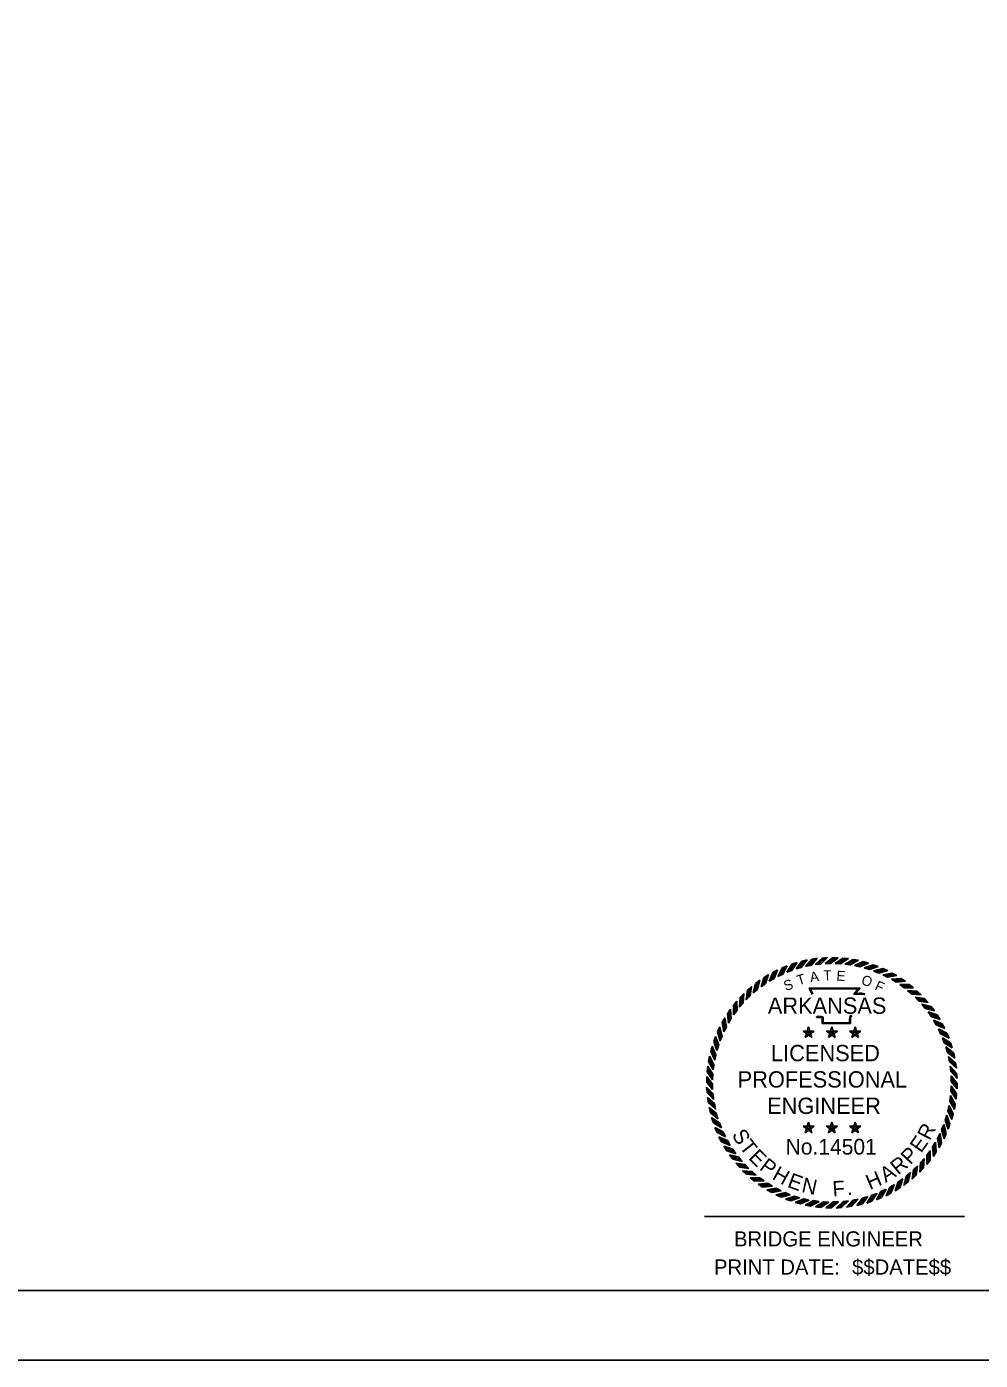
# Model space of a CAD drawing. Extents: x 188 to 14744886, y 129 to 1829278.
# Drawn here: x 206.58 to 214.44, y 128.51 to 139.51 of the extents above; entities that cross this region are included whole.
import ezdxf

# ---------------------------------------------------------------- set-up
doc = ezdxf.new("R2010")
doc.units = 0
for name, color, linetype in [('B_border', 7, 'Continuous'), ('B_Print_Date_Text', 7, 'Continuous'), ('B_Text', 7, 'Continuous'), ('R_Border', 7, 'Continuous'), ('STAMP', 7, 'Continuous')]:
    doc.layers.add(name, color=color, linetype=linetype)

msp = doc.modelspace()

# ---------------------------------------------------------------- linework, layer by layer
at = {"layer": 'B_border'}
msp.add_line((212.167, 129.699), (214.309, 129.699), dxfattribs=at)
msp.add_line((212.167, 129.699), (214.309, 129.699), dxfattribs=at)
at = {"layer": 'R_Border'}
msp.add_line((221.306, 129.091), (189.399, 129.091), dxfattribs=at)
msp.add_lwpolyline([(187.883, 150.514), (221.883, 150.514), (221.883, 128.514), (187.883, 128.514)], close=True, dxfattribs=at)
at = {"layer": 'STAMP'}
for p, q in [((212.886, 131.781), (212.929, 131.796)), ((212.968, 131.805), (213.012, 131.816)), ((213.052, 131.822), (213.096, 131.83)), ((213.079, 131.778), (213.124, 131.782)), ((213.136, 131.832), (213.181, 131.836)), ((213.16, 131.786), (213.206, 131.786)), ((213.222, 131.834), (213.267, 131.834)), ((213.242, 131.787), (213.287, 131.784)), ((213.307, 131.831), (213.352, 131.828)), ((213.323, 131.782), (213.368, 131.775)), ((213.391, 131.82), (213.436, 131.813)), ((213.475, 131.802), (213.519, 131.791)), ((212.656, 131.67), (212.694, 131.695)), ((212.73, 131.713), (212.769, 131.735)), ((212.77, 131.681), (212.811, 131.699)), ((212.807, 131.75), (212.848, 131.769)), ((212.844, 131.715), (212.887, 131.73)), ((212.921, 131.742), (212.964, 131.754)), ((212.999, 131.764), (213.044, 131.771)), ((213.403, 131.77), (213.447, 131.759)), ((213.482, 131.751), (213.526, 131.737)), ((213.556, 131.777), (213.599, 131.763)), ((213.56, 131.726), (213.602, 131.708)), ((213.635, 131.694), (213.675, 131.673)), ((213.636, 131.746), (213.677, 131.728)), ((213.712, 131.708), (213.752, 131.687)), ((212.521, 131.566), (212.554, 131.597)), ((212.568, 131.544), (212.604, 131.573)), ((212.587, 131.621), (212.622, 131.649)), ((212.632, 131.595), (212.669, 131.621)), ((212.699, 131.641), (212.739, 131.663)), ((213.707, 131.657), (213.745, 131.632)), ((213.776, 131.613), (213.812, 131.586)), ((213.785, 131.664), (213.823, 131.64)), ((213.841, 131.564), (213.875, 131.534)), ((213.854, 131.614), (213.89, 131.587)), ((212.405, 131.441), (212.433, 131.477)), ((212.455, 131.428), (212.485, 131.461)), ((212.461, 131.506), (212.491, 131.539)), ((212.509, 131.488), (212.542, 131.519)), ((213.902, 131.51), (213.933, 131.477)), ((213.919, 131.559), (213.953, 131.528)), ((213.958, 131.451), (213.986, 131.416)), ((213.979, 131.498), (214.01, 131.465)), ((212.355, 131.372), (212.38, 131.41)), ((212.406, 131.363), (212.434, 131.399)), ((214.009, 131.388), (214.034, 131.35)), ((214.034, 131.433), (214.062, 131.397)), ((214.083, 131.363), (214.108, 131.325)), ((212.274, 131.222), (212.291, 131.264)), ((212.311, 131.299), (212.333, 131.339)), ((212.325, 131.222), (212.346, 131.262)), ((212.363, 131.294), (212.387, 131.332)), ((213.07, 131.23), (212.979, 131.23)), ((212.979, 131.23), (213.053, 131.177)), ((213.024, 131.264), (212.996, 131.177)), ((212.996, 131.177), (213.07, 131.23)), ((213.052, 131.177), (213.024, 131.264)), ((213.262, 131.23), (213.17, 131.23)), ((213.171, 131.23), (213.244, 131.177)), ((213.216, 131.264), (213.188, 131.177)), ((213.188, 131.177), (213.262, 131.23)), ((213.244, 131.177), (213.216, 131.264)), ((213.454, 131.23), (213.362, 131.23)), ((213.362, 131.23), (213.436, 131.177)), ((213.408, 131.264), (213.38, 131.177)), ((213.38, 131.177), (213.454, 131.23)), ((213.436, 131.177), (213.408, 131.264)), ((214.054, 131.32), (214.076, 131.281)), ((214.094, 131.249), (214.113, 131.208)), ((214.126, 131.29), (214.148, 131.25)), ((212.242, 131.143), (212.256, 131.186)), ((212.293, 131.147), (212.311, 131.188)), ((213.018, 131.216), (213.031, 131.216)), ((213.024, 131.221), (213.024, 131.209)), ((213.21, 131.216), (213.223, 131.216)), ((213.216, 131.221), (213.216, 131.209)), ((213.402, 131.216), (213.415, 131.216)), ((213.408, 131.221), (213.408, 131.209)), ((214.128, 131.175), (214.143, 131.133)), ((214.163, 131.213), (214.182, 131.171)), ((214.194, 131.133), (214.209, 131.09)), ((212.199, 130.978), (212.206, 131.023)), ((212.217, 131.061), (212.228, 131.105)), ((212.25, 130.99), (212.26, 131.034)), ((212.268, 131.069), (212.283, 131.112)), ((214.156, 131.099), (214.167, 131.055)), ((214.177, 131.02), (214.185, 130.976)), ((214.218, 131.051), (214.229, 131.008)), ((212.188, 130.894), (212.192, 130.939)), ((212.237, 130.91), (212.244, 130.954)), ((214.191, 130.94), (214.196, 130.895)), ((214.235, 130.968), (214.243, 130.923)), ((212.184, 130.808), (212.184, 130.854)), ((212.232, 130.828), (212.235, 130.874)), ((212.233, 130.747), (212.233, 130.792)), ((214.199, 130.859), (214.2, 130.814)), ((214.245, 130.883), (214.249, 130.838)), ((214.248, 130.798), (214.248, 130.753)), ((212.188, 130.723), (212.183, 130.768)), ((212.198, 130.638), (212.19, 130.683)), ((212.241, 130.666), (212.237, 130.711)), ((214.195, 130.697), (214.188, 130.652)), ((214.201, 130.778), (214.197, 130.733)), ((214.244, 130.713), (214.241, 130.668)), ((212.215, 130.555), (212.203, 130.599)), ((212.256, 130.586), (212.248, 130.631)), ((214.183, 130.616), (214.172, 130.572)), ((214.233, 130.628), (214.226, 130.583)), ((212.239, 130.473), (212.224, 130.516)), ((212.277, 130.507), (212.265, 130.551)), ((212.305, 130.431), (212.29, 130.474)), ((213.024, 130.477), (212.996, 130.39)), ((213.052, 130.39), (213.024, 130.477)), ((213.216, 130.477), (213.188, 130.39)), ((213.244, 130.39), (213.216, 130.477)), ((213.408, 130.477), (213.38, 130.39)), ((213.436, 130.39), (213.408, 130.477)), ((214.164, 130.537), (214.15, 130.494)), ((214.19, 130.463), (214.176, 130.42)), ((214.215, 130.545), (214.204, 130.501)), ((212.269, 130.393), (212.251, 130.435)), ((212.306, 130.317), (212.284, 130.356)), ((212.339, 130.357), (212.32, 130.398)), ((213.07, 130.444), (212.979, 130.444)), ((212.979, 130.444), (213.053, 130.39)), ((212.996, 130.39), (213.07, 130.444)), ((213.018, 130.429), (213.031, 130.429)), ((213.024, 130.434), (213.024, 130.422)), ((213.262, 130.444), (213.17, 130.444)), ((213.171, 130.444), (213.244, 130.39)), ((213.188, 130.39), (213.262, 130.444)), ((213.21, 130.429), (213.223, 130.429)), ((213.216, 130.434), (213.216, 130.422)), ((213.454, 130.444), (213.362, 130.444)), ((213.362, 130.444), (213.436, 130.39)), ((213.38, 130.39), (213.454, 130.444)), ((213.402, 130.429), (213.415, 130.429)), ((213.408, 130.434), (213.408, 130.422)), ((214.108, 130.384), (214.086, 130.344)), ((214.139, 130.46), (214.121, 130.418)), ((214.159, 130.384), (214.141, 130.342)), ((212.35, 130.243), (212.325, 130.281)), ((212.378, 130.286), (212.356, 130.326)), ((212.424, 130.218), (212.399, 130.256)), ((214.026, 130.243), (213.999, 130.207)), ((214.07, 130.312), (214.045, 130.274)), ((214.121, 130.307), (214.1, 130.267)), ((212.399, 130.174), (212.371, 130.209)), ((212.454, 130.108), (212.423, 130.141)), ((212.475, 130.155), (212.447, 130.191)), ((213.977, 130.178), (213.947, 130.145)), ((214.027, 130.165), (214, 130.129)), ((214.077, 130.234), (214.053, 130.196)), ((212.514, 130.048), (212.48, 130.078)), ((212.531, 130.096), (212.5, 130.129)), ((212.592, 130.042), (212.558, 130.072)), ((212.657, 129.993), (212.621, 130.02)), ((213.864, 130.062), (213.829, 130.034)), ((213.911, 130.04), (213.878, 130.009)), ((213.923, 130.118), (213.89, 130.087)), ((213.972, 130.1), (213.941, 130.067)), ((212.578, 129.992), (212.542, 130.02)), ((212.648, 129.942), (212.609, 129.967)), ((212.721, 129.898), (212.681, 129.919)), ((212.725, 129.949), (212.687, 129.974)), ((212.798, 129.912), (212.758, 129.933)), ((213.662, 129.925), (213.621, 129.907)), ((213.733, 129.965), (213.694, 129.943)), ((213.776, 129.936), (213.739, 129.911)), ((213.801, 130.011), (213.763, 129.986)), ((213.846, 129.986), (213.81, 129.958)), ((212.797, 129.86), (212.755, 129.878)), ((212.873, 129.88), (212.831, 129.898)), ((212.876, 129.829), (212.833, 129.843)), ((212.95, 129.855), (212.907, 129.869)), ((212.958, 129.804), (212.914, 129.815)), ((213.029, 129.836), (212.985, 129.847)), ((213.11, 129.824), (213.065, 129.831)), ((213.191, 129.819), (213.146, 129.822)), ((213.272, 129.82), (213.227, 129.82)), ((213.353, 129.828), (213.308, 129.824)), ((213.433, 129.843), (213.389, 129.835)), ((213.464, 129.802), (213.421, 129.79)), ((213.512, 129.864), (213.468, 129.852)), ((213.546, 129.826), (213.504, 129.81)), ((213.588, 129.891), (213.546, 129.876)), ((213.626, 129.856), (213.585, 129.838)), ((213.703, 129.893), (213.663, 129.871)), ((213.041, 129.786), (212.997, 129.793)), ((213.126, 129.775), (213.081, 129.779)), ((213.211, 129.771), (213.166, 129.771)), ((213.296, 129.774), (213.251, 129.77)), ((213.381, 129.785), (213.336, 129.777))]:
    msp.add_line(p, q, dxfattribs=at)
for points in [[(212.844, 131.715), (212.886, 131.781)], [(212.858, 131.719), (212.9, 131.785)], [(212.873, 131.725), (212.915, 131.791)], [(212.887, 131.73), (212.929, 131.796)], [(212.921, 131.742), (212.968, 131.805)], [(212.935, 131.746), (212.982, 131.808)], [(212.95, 131.75), (212.997, 131.812)], [(212.964, 131.754), (213.012, 131.816)], [(212.999, 131.763), (213.052, 131.822)], [(213.014, 131.766), (213.066, 131.824)], [(213.029, 131.769), (213.081, 131.827)], [(213.044, 131.771), (213.096, 131.83)], [(213.079, 131.778), (213.136, 131.832)], [(213.094, 131.779), (213.151, 131.833)], [(213.109, 131.781), (213.166, 131.835)], [(213.124, 131.782), (213.181, 131.836)], [(213.16, 131.786), (213.222, 131.834)], [(213.175, 131.786), (213.236, 131.834)], [(213.19, 131.786), (213.252, 131.834)], [(213.206, 131.786), (213.267, 131.834)], [(213.242, 131.787), (213.307, 131.831)], [(213.256, 131.786), (213.321, 131.83)], [(213.272, 131.785), (213.337, 131.829)], [(213.287, 131.784), (213.352, 131.828)], [(213.323, 131.782), (213.391, 131.82)], [(213.337, 131.78), (213.406, 131.818)], [(213.353, 131.777), (213.421, 131.815)], [(213.368, 131.775), (213.436, 131.813)], [(213.403, 131.77), (213.475, 131.802)], [(213.417, 131.766), (213.489, 131.798)], [(213.433, 131.763), (213.504, 131.795)], [(213.447, 131.759), (213.519, 131.791)], [(212.644, 131.603), (212.669, 131.678)], [(212.657, 131.612), (212.681, 131.687)], [(212.669, 131.621), (212.694, 131.695)], [(212.699, 131.641), (212.73, 131.713)], [(212.712, 131.648), (212.743, 131.72)], [(212.725, 131.656), (212.756, 131.728)], [(212.739, 131.663), (212.769, 131.735)], [(212.77, 131.681), (212.807, 131.75)], [(212.783, 131.687), (212.82, 131.756)], [(212.798, 131.693), (212.834, 131.763)], [(212.811, 131.699), (212.848, 131.769)], [(213.482, 131.751), (213.556, 131.777)], [(213.496, 131.746), (213.57, 131.773)], [(213.511, 131.742), (213.585, 131.768)], [(213.525, 131.737), (213.599, 131.763)], [(213.56, 131.726), (213.635, 131.746)], [(213.573, 131.72), (213.649, 131.74)], [(213.588, 131.714), (213.663, 131.734)], [(213.602, 131.708), (213.677, 131.728)], [(213.635, 131.694), (213.712, 131.708)], [(213.648, 131.687), (213.725, 131.701)], [(213.662, 131.68), (213.739, 131.694)], [(213.675, 131.673), (213.752, 131.687)], [(212.509, 131.488), (212.521, 131.566)], [(212.52, 131.498), (212.532, 131.576)], [(212.531, 131.509), (212.543, 131.587)], [(212.542, 131.519), (212.554, 131.597)], [(212.568, 131.544), (212.587, 131.62)], [(212.58, 131.553), (212.598, 131.629)], [(212.592, 131.563), (212.61, 131.639)], [(212.604, 131.573), (212.622, 131.649)], [(212.632, 131.595), (212.656, 131.67)], [(213.053, 131.532), (213.029, 131.584), (213.447, 131.584), (213.412, 131.54), (213.44, 131.541), (213.464, 131.541), (213.487, 131.538)], [(213.059, 131.534), (213.04, 131.577), (213.433, 131.577), (213.398, 131.533), (213.44, 131.534), (213.463, 131.534), (213.487, 131.532)], [(213.707, 131.657), (213.785, 131.664)], [(213.719, 131.649), (213.797, 131.656)], [(213.733, 131.641), (213.811, 131.648)], [(213.745, 131.632), (213.823, 131.64)], [(213.776, 131.613), (213.854, 131.614)], [(213.787, 131.604), (213.866, 131.605)], [(213.8, 131.595), (213.878, 131.596)], [(213.812, 131.586), (213.89, 131.587)], [(213.841, 131.564), (213.919, 131.559)], [(212.415, 131.374), (212.414, 131.452)], [(212.424, 131.387), (212.423, 131.465)], [(212.434, 131.399), (212.433, 131.477)], [(212.455, 131.428), (212.461, 131.506)], [(212.465, 131.438), (212.471, 131.516)], [(212.475, 131.45), (212.481, 131.528)], [(212.485, 131.461), (212.491, 131.539)], [(213.852, 131.554), (213.93, 131.549)], [(213.863, 131.544), (213.941, 131.539)], [(213.875, 131.534), (213.953, 131.528)], [(213.902, 131.51), (213.979, 131.498)], [(213.911, 131.499), (213.989, 131.487)], [(213.922, 131.488), (214, 131.476)], [(213.933, 131.477), (214.01, 131.465)], [(213.958, 131.451), (214.034, 131.433)], [(212.363, 131.294), (212.355, 131.372)], [(212.371, 131.306), (212.363, 131.384)], [(212.379, 131.319), (212.372, 131.397)], [(212.387, 131.332), (212.38, 131.41)], [(212.406, 131.363), (212.405, 131.441)], [(213.381, 131.357), (213.374, 131.351), (213.371, 131.342), (213.369, 131.321), (213.369, 131.292), (213.136, 131.292), (213.136, 131.331), (213.136, 131.339), (213.127, 131.342), (213.093, 131.342), (213.088, 131.351)], [(213.377, 131.362), (213.368, 131.355), (213.365, 131.343), (213.362, 131.321), (213.362, 131.298), (213.143, 131.298), (213.143, 131.331), (213.143, 131.344), (213.128, 131.349), (213.097, 131.349), (213.093, 131.355)], [(213.967, 131.44), (214.043, 131.421)], [(213.977, 131.428), (214.053, 131.409)], [(213.986, 131.416), (214.062, 131.397)], [(214.009, 131.388), (214.083, 131.363)], [(214.017, 131.376), (214.091, 131.351)], [(214.026, 131.363), (214.1, 131.338)], [(214.034, 131.35), (214.108, 131.325)], [(212.299, 131.16), (212.279, 131.236)], [(212.305, 131.175), (212.285, 131.25)], [(212.311, 131.188), (212.291, 131.264)], [(212.325, 131.222), (212.311, 131.299)], [(212.332, 131.234), (212.318, 131.312)], [(212.339, 131.249), (212.325, 131.326)], [(212.346, 131.262), (212.333, 131.339)], [(214.054, 131.32), (214.126, 131.29)], [(214.061, 131.307), (214.133, 131.277)], [(214.069, 131.294), (214.141, 131.263)], [(214.076, 131.281), (214.148, 131.25)], [(214.094, 131.249), (214.163, 131.213)], [(214.1, 131.236), (214.169, 131.199)], [(212.268, 131.069), (212.242, 131.143)], [(212.273, 131.083), (212.247, 131.157)], [(212.278, 131.098), (212.251, 131.172)], [(212.283, 131.112), (212.256, 131.186)], [(212.294, 131.147), (212.274, 131.222)], [(214.107, 131.222), (214.176, 131.185)], [(214.113, 131.208), (214.182, 131.171)], [(214.128, 131.175), (214.194, 131.133)], [(214.133, 131.162), (214.199, 131.119)], [(214.138, 131.147), (214.204, 131.105)], [(214.143, 131.133), (214.209, 131.09)], [(212.244, 130.954), (212.206, 131.023)], [(212.25, 130.99), (212.217, 131.061)], [(212.253, 131.004), (212.221, 131.076)], [(212.257, 131.02), (212.224, 131.091)], [(212.26, 131.034), (212.228, 131.105)], [(214.155, 131.099), (214.218, 131.051)], [(214.159, 131.085), (214.221, 131.037)], [(214.163, 131.07), (214.226, 131.022)], [(214.167, 131.055), (214.229, 131.007)], [(214.177, 131.02), (214.235, 130.968)], [(212.234, 130.859), (212.19, 130.924)], [(212.233, 130.843), (212.19, 130.908)], [(212.235, 130.874), (212.192, 130.939)], [(212.237, 130.91), (212.199, 130.978)], [(212.24, 130.924), (212.202, 130.992)], [(212.242, 130.94), (212.204, 131.008)], [(214.179, 131.006), (214.237, 130.953)], [(214.182, 130.99), (214.24, 130.938)], [(214.185, 130.976), (214.243, 130.923)], [(214.191, 130.94), (214.245, 130.883)], [(214.193, 130.926), (214.246, 130.869)], [(214.194, 130.91), (214.248, 130.853)], [(212.233, 130.792), (212.184, 130.854)], [(212.233, 130.777), (212.184, 130.839)], [(212.233, 130.762), (212.185, 130.823)], [(212.233, 130.747), (212.185, 130.808)], [(212.232, 130.828), (212.188, 130.893)], [(214.196, 130.895), (214.249, 130.838)], [(214.199, 130.859), (214.248, 130.798)], [(214.199, 130.845), (214.248, 130.783)], [(214.2, 130.829), (214.249, 130.768)], [(214.2, 130.814), (214.249, 130.753)], [(212.237, 130.711), (212.183, 130.768)], [(212.238, 130.696), (212.185, 130.753)], [(212.24, 130.681), (212.186, 130.738)], [(212.241, 130.666), (212.188, 130.723)], [(212.248, 130.631), (212.19, 130.683)], [(214.193, 130.682), (214.231, 130.614)], [(214.195, 130.697), (214.233, 130.628)], [(214.197, 130.733), (214.241, 130.667)], [(214.199, 130.763), (214.243, 130.698)], [(214.199, 130.748), (214.242, 130.682)], [(214.201, 130.778), (214.244, 130.713)], [(212.25, 130.616), (212.192, 130.668)], [(212.253, 130.6), (212.195, 130.653)], [(212.256, 130.586), (212.198, 130.638)], [(212.265, 130.551), (212.203, 130.599)], [(212.269, 130.537), (212.207, 130.584)], [(214.172, 130.572), (214.205, 130.501)], [(214.176, 130.587), (214.208, 130.515)], [(214.179, 130.602), (214.212, 130.531)], [(214.183, 130.616), (214.215, 130.545)], [(214.188, 130.652), (214.226, 130.583)], [(214.191, 130.667), (214.229, 130.598)], [(212.274, 130.522), (212.211, 130.569)], [(212.277, 130.507), (212.215, 130.555)], [(212.29, 130.474), (212.224, 130.516)], [(212.294, 130.459), (212.228, 130.501)], [(212.3, 130.445), (212.234, 130.487)], [(212.305, 130.431), (212.239, 130.473)], [(214.15, 130.494), (214.176, 130.42)], [(214.155, 130.508), (214.181, 130.434)], [(214.16, 130.523), (214.186, 130.449)], [(214.164, 130.537), (214.19, 130.463)], [(212.32, 130.398), (212.251, 130.435)], [(212.326, 130.384), (212.257, 130.421)], [(212.333, 130.37), (212.263, 130.407)], [(212.339, 130.357), (212.269, 130.393)], [(212.356, 130.326), (212.284, 130.356)], [(214.094, 130.358), (214.107, 130.281)], [(214.101, 130.372), (214.114, 130.295)], [(214.108, 130.385), (214.121, 130.307)], [(214.121, 130.418), (214.141, 130.342)], [(214.127, 130.432), (214.147, 130.356)], [(214.133, 130.446), (214.153, 130.371)], [(214.139, 130.46), (214.159, 130.384)], [(212.364, 130.312), (212.292, 130.343)], [(212.371, 130.299), (212.299, 130.329)], [(212.378, 130.286), (212.306, 130.317)], [(212.399, 130.256), (212.324, 130.281)], [(212.407, 130.244), (212.333, 130.268)], [(212.416, 130.231), (212.342, 130.255)], [(212.424, 130.218), (212.35, 130.243)], [(214.026, 130.244), (214.027, 130.165)], [(214.046, 130.274), (214.053, 130.196)], [(214.054, 130.287), (214.061, 130.209)], [(214.062, 130.3), (214.069, 130.222)], [(214.07, 130.312), (214.077, 130.234)], [(214.086, 130.344), (214.1, 130.267)], [(212.447, 130.191), (212.371, 130.209)], [(212.456, 130.179), (212.38, 130.197)], [(212.466, 130.167), (212.39, 130.185)], [(212.475, 130.155), (212.399, 130.173)], [(212.5, 130.129), (212.423, 130.141)], [(212.51, 130.118), (212.433, 130.13)], [(213.947, 130.145), (213.941, 130.067)], [(213.957, 130.156), (213.952, 130.078)], [(213.968, 130.168), (213.962, 130.09)], [(213.977, 130.179), (213.972, 130.1)], [(213.999, 130.207), (214, 130.129)], [(214.008, 130.219), (214.009, 130.141)], [(214.018, 130.232), (214.018, 130.154)], [(212.521, 130.107), (212.444, 130.119)], [(212.531, 130.096), (212.454, 130.108)], [(212.558, 130.072), (212.48, 130.078)], [(212.569, 130.062), (212.491, 130.068)], [(212.581, 130.052), (212.503, 130.057)], [(212.592, 130.042), (212.514, 130.048)], [(212.621, 130.02), (212.542, 130.02)], [(213.829, 130.034), (213.81, 129.957)], [(213.841, 130.043), (213.822, 129.967)], [(213.853, 130.053), (213.834, 129.977)], [(213.864, 130.062), (213.846, 129.986)], [(213.89, 130.087), (213.878, 130.009)], [(213.901, 130.097), (213.889, 130.02)], [(213.913, 130.108), (213.901, 130.031)], [(213.923, 130.118), (213.911, 130.04)], [(212.633, 130.011), (212.554, 130.01)], [(212.645, 130.002), (212.567, 130.001)], [(212.657, 129.993), (212.578, 129.992)], [(212.687, 129.974), (212.609, 129.967)], [(212.7, 129.966), (212.622, 129.958)], [(212.713, 129.957), (212.635, 129.95)], [(212.726, 129.949), (212.648, 129.942)], [(212.758, 129.933), (212.681, 129.919)], [(212.771, 129.926), (212.694, 129.912)], [(212.785, 129.919), (212.708, 129.905)], [(212.798, 129.912), (212.721, 129.898)], [(213.635, 129.913), (213.598, 129.844)], [(213.649, 129.92), (213.613, 129.85)], [(213.663, 129.925), (213.626, 129.856)], [(213.694, 129.943), (213.663, 129.871)], [(213.707, 129.95), (213.676, 129.878)], [(213.721, 129.958), (213.69, 129.886)], [(213.733, 129.965), (213.703, 129.893)], [(213.763, 129.986), (213.739, 129.911)], [(213.776, 129.994), (213.751, 129.92)], [(213.789, 130.003), (213.764, 129.929)], [(213.801, 130.011), (213.776, 129.937)], [(212.831, 129.898), (212.755, 129.878)], [(212.845, 129.892), (212.769, 129.872)], [(212.859, 129.886), (212.784, 129.866)], [(212.873, 129.88), (212.797, 129.86)], [(212.907, 129.869), (212.833, 129.843)], [(212.921, 129.864), (212.848, 129.838)], [(212.936, 129.86), (212.863, 129.834)], [(212.95, 129.855), (212.876, 129.829)], [(212.985, 129.847), (212.914, 129.815)], [(213, 129.843), (212.928, 129.811)], [(213.015, 129.84), (212.944, 129.808)], [(213.029, 129.836), (212.958, 129.804)], [(213.065, 129.831), (212.997, 129.793)], [(213.08, 129.829), (213.011, 129.791)], [(213.095, 129.827), (213.027, 129.789)], [(213.11, 129.824), (213.041, 129.786)], [(213.146, 129.822), (213.081, 129.779)], [(213.161, 129.821), (213.096, 129.777)], [(213.176, 129.82), (213.111, 129.777)], [(213.191, 129.819), (213.126, 129.775)], [(213.227, 129.82), (213.166, 129.771)], [(213.242, 129.82), (213.181, 129.771)], [(213.258, 129.82), (213.197, 129.771)], [(213.272, 129.82), (213.211, 129.771)], [(213.308, 129.824), (213.251, 129.77)], [(213.323, 129.825), (213.266, 129.771)], [(213.339, 129.827), (213.282, 129.773)], [(213.353, 129.828), (213.296, 129.774)], [(213.389, 129.835), (213.336, 129.777)], [(213.404, 129.837), (213.351, 129.779)], [(213.419, 129.84), (213.367, 129.782)], [(213.433, 129.843), (213.381, 129.785)], [(213.468, 129.852), (213.421, 129.79)], [(213.483, 129.856), (213.435, 129.794)], [(213.498, 129.86), (213.45, 129.798)], [(213.512, 129.864), (213.465, 129.802)], [(213.546, 129.876), (213.504, 129.81)], [(213.56, 129.881), (213.518, 129.815)], [(213.575, 129.887), (213.533, 129.821)], [(213.589, 129.892), (213.546, 129.826)], [(213.621, 129.907), (213.585, 129.837)]]:
    msp.add_lwpolyline(points, dxfattribs=at)

# ---------------------------------------------------------------- texts
at = {"layer": 'B_Print_Date_Text'}
msp.add_text('PRINT DATE:', height=0.1248, dxfattribs=at).set_placement((212.244, 129.221))
msp.add_text('$$DATE$$', height=0.1248, rotation=359.9999, dxfattribs=at).set_placement((213.383, 129.221))
at = {"layer": 'B_Text'}
msp.add_text('BRIDGE ENGINEER', height=0.1248, dxfattribs=at).set_placement((212.409, 129.453))
at = {"layer": 'STAMP'}
for s, height, rotation, p in [('T', 0.0823, 16.9015, (212.941, 131.606)), ('A', 0.0823, 8.6788, (213.041, 131.632)), ('T', 0.0823, 1.4789, (213.147, 131.648)), ('E', 0.0823, 356.672, (213.252, 131.646)), ('O', 0.0823, 341.2218, (213.452, 131.618)), ('S', 0.0823, 19.7726, (212.836, 131.559)), ('F', 0.0823, 335.3628, (213.563, 131.574)), ('R', 0.125, 62.6418, (214.024, 130.32)), ('S', 0.125, 300.7985, (212.387, 130.375)), ('E', 0.125, 54.981, (213.952, 130.218)), ('T', 0.125, 308.0945, (212.448, 130.273)), ('E', 0.125, 315.3905, (212.522, 130.179)), ('P', 0.125, 46.9554, (213.863, 130.121)), ('P', 0.125, 323.0513, (212.611, 130.092)), ('R', 0.125, 38.9298, (213.762, 130.038)), ('H', 0.125, 331.0769, (212.716, 130.013)), ('E', 0.125, 339.8321, (212.842, 129.946)), ('N', 0.125, 347.4929, (212.96, 129.903)), ('H', 0.125, 22.8786, (213.529, 129.918)), ('A', 0.125, 31.6338, (213.66, 129.976)), ('F', 0.125, 3.9089, (213.225, 129.866)), ('.', 0.125, 11.205, (213.344, 129.874))]:
    msp.add_text(s, height=height, rotation=rotation, dxfattribs=at).set_placement(p)
for s, height, p in [('ARKANSAS', 0.1343, (212.688, 131.372)), ('LICENSED', 0.1343, (212.714, 130.981)), ('PROFESSIONAL', 0.13433, (212.439, 130.764)), ('ENGINEER', 0.1343, (212.682, 130.546)), ('No.14501', 0.1295, (212.835, 130.211))]:
    msp.add_text(s, height=height, dxfattribs=at).set_placement(p)

doc.saveas('drawing.dxf')
